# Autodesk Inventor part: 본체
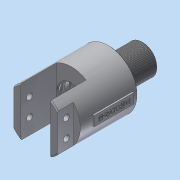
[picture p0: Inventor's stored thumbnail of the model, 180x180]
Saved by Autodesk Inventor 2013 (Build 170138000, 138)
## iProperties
Created: 2019-02
Part Number: 본체
Material: 알루미늄 6061
Document SubType Name: Modeling
Designer: Administrator
Density: 2.71 g/cm^3
Mass: 347.812 g
Surface Area: 290.077 cm^2
Volume: 128.344 cm^3
Author: Administrator
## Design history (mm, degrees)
sketch "스케치1"
  geometry: C1 r 29 at (0, 0); 1 further point
  constraints: 1 centre point, 1 coincident
  dimensions: "d0" = 58 diameter of C1
extrude "돌출1" new body sketch "스케치1" stored distance "d1" = 74; taper "d2" = 0 deg
sketch "스케치6"
  geometry: L1 (22, 18.894)-(22, -18.894); L2 (-22, -18.894)-(-22, 18.894); L3 (0, -29)-(0, 29); A1 r 29 centre (0, 0) between (22, 18.894) and (22, -18.894) reference; A2 r 29 centre (0, 0) between (-22, 18.894) and (-22, -18.894); A3 r 29 centre (0, 0) between (0, 29) and (-22, 18.894); A4 r 29 centre (0, 0) between (-22, -18.894) and (22, -18.894); A5 r 29 centre (0, 0) between (22, -18.894) and (22, 18.894); A6 r 29 centre (0, 0) between (22, 18.894) and (0, 29); 3 further points
  constraints: 16 point on circle, 6 end point, 5 centre point, 4 midpoint, 2 horizontal alignment, 2 parallel, 1 coincident, 1 vertical, 1 other
  dimensions: "d16" = 44 distance between parallel lines of L1 L2
extrude "돌출3" cut sketch "스케치6" distance "d18" = 16; taper "d19" = 0 deg
sketch "스케치7"
  geometry: L1 (22, -18.894)-(22, 18.894) reference; L2 (-22, 18.894)-(-22, -18.894) reference; L3 (-15, -24.819)-(-15, 24.819); L4 (15, 24.819)-(15, -24.819); A1 r 29 centre (0, 0) between (22, 18.894) and (-22, 18.894) reference; A2 r 29 centre (0, 0) between (-22, -18.894) and (22, -18.894) reference; A3 r 29 centre (0, 0) between (-22, 18.894) and (-15, -24.819); A4 r 29 centre (0, 0) between (-15, 24.819) and (-22, 18.894); A5 r 29 centre (0, 0) between (-15, -24.819) and (15, -24.819); A6 r 29 centre (0, 0) between (22, -18.894) and (15, 24.819); A7 r 29 centre (0, 0) between (15, -24.819) and (22, -18.894); A8 r 29 centre (0, 0) between (15, 24.819) and (-15, 24.819)
  constraints: 16 point on circle, 6 centre point, 6 end point, 1 coincident, 1 concentric
  dimensions: "d20" = 7 distance between parallel lines of L3 L2; "d21" = 7 distance between parallel lines of L1 L4 (= d20)
extrude "돌출4" cut sketch "스케치7" distance "d22" = 36; taper "d23" = 0 deg
sketch "스케치9"
  geometry: C1 r 29 at (0, 0) reference; C2 r 13 at (0, 0)
  constraints: 1 centre point, 1 coincident
  dimensions: "d28" = 26 diameter of C2
extrude "돌출5" join sketch "스케치9" distance "d29" = 5; taper "d30" = 0 deg
sketch "스케치10"
  geometry: C1 r 13 at (0, 0) reference; C2 r 15 at (0, 0)
  constraints: 1 centre point, 1 coincident
  dimensions: "d31" = 30 diameter of C2
extrude "돌출6" join sketch "스케치10" distance "d32" = 29; taper "d33" = 0 deg
sketch "스케치11"
  geometry: L1 (37.789, 0)-(0, 0) reference; L2 (37.789, 16)-(0, 16) reference; L3 (18.894, 0)-(18.894, 16); L4 (37.789, 74)-(37.789, 16) reference; L5 (37.789, 16)-(37.789, 0) reference; L6 (37.789, 0)-(0, 0) reference; L7 (0, 0)-(0, 16) reference; L8 (37.789, 16)-(0, 16) reference; L9 (0, 74)-(37.789, 74) reference; L10 (0, 16)-(0, 74) reference; C1 r 3 at (27.894, 9); C2 r 3 at (9.894, 9); 1 further point
  constraints: 2 centre point, 2 end point, 2 midpoint, 1 symmetric about line, 1 other
  dimensions: "d37" = 6 diameter of C1; "d38" = 9 distance from line of C1.centre L1; "d39" = 9 distance from line of C1.centre L3
extrude "돌출7" cut sketch "스케치11" stored distance "d40" = 29; taper "d41" = 0 deg
sketch "스케치12"
  geometry: L1 (-1, -24.819)-(-1, 24.819) reference; L2 (-1, 0)-(-1, 14); L3 (-1, 14)-(1.65, 14); L4 (1.65, 14)-(1.65, 17); L5 (1.65, 17)-(6.35, 17); L6 (6.35, 17)-(6.35, 14); L7 (6.35, 14)-(10.65, 14); L8 (10.65, 14)-(10.65, 17); L9 (10.65, 17)-(15.35, 17); L10 (15.35, 17)-(15.35, 14); L11 (15.35, 14)-(19, 14); L12 (19, 14)-(19, 16); L13 (19, 16)-(26, 16); L14 (71, 7)-(49, 7); L15 (49, 7)-(49, 4); L16 (49, 4)-(26, 4); L17 (26, 4)-(26, 16); L18 (71, -15)-(71, 15) reference; L19 (71, 7)-(71, 0); L20 (-1, 0)-(71, 0); 1 further point
  constraints: 36 end point, 7 parallel, 6 collinear, 3 perpendicular, 2 midpoint, 2 point on line, 1 horizontal alignment
  dimensions: "d48" = 7 distance of L12.end L13.end; "d49" = 4.7 distance of L4.end L5.end; "d50" = 4.7 distance of L8.end L9.end; "d51" = 2.65 distance of L2.end L3.end (computed from d49); "d52" = 4.3 distance of L6.end L7.end; "d54" = 3.65 distance of L10.end L11.end (computed from d49, d50, d52, d51); "d57" = 22 distance of L14.start L14.end; "d58" = 23 distance of L15.end L16.end; "d59" = 12 distance of L16.end L13.end; "d60" = 28 diameter of L3 L20; "d61" = 34 diameter of L5 L20; "d62" = 8 diameter of L16 L20; "d63" = 14 diameter of L14 L20; "d64" = 32 diameter of L13 L20
revolve "회전1" sketch "스케치12" stored, may be unused: angle "d65" = 90 deg
sketch "스케치13"
  geometry: C1 r 7 at (0, 0) reference
hole "구멍1" sketch "스케치13" at (0, 0) diameter "d66" = 11.835; stored, may be unused: countersink angle "d70" = 90 deg, drill point angle "d72" = 118 deg; dims "d67" = 18, "d68" = 4, "d69" = 2, "d71" = 22
sketch "스케치14"
  geometry: C1 r 7 at (0, 0) reference; C2 r 15 at (0, 0) reference; C3 r 7 at (0, 0)
  constraints: 1 centre point, 1 coincident
  dimensions: "d73" = 14 diameter of C3
extrude "돌출8" join sketch "스케치14" distance "d74" = 22; taper "d75" = 0 deg
sketch "스케치15"
  geometry: C1 r 15 at (0, 0) reference
hole "구멍2" sketch "스케치15" at (0, 0) diameter "d76" = 11.835; stored, may be unused: countersink angle "d80" = 90 deg, drill point angle "d82" = 118 deg; dims "d77" = 18, "d78" = 4, "d79" = 2, "d81" = 22
feature "스레드1" dims "d83" = 10, "d84" = 0
chamfer "모따기1" distance "d85" = 1; stored, may be unused: second distance "d86" = 2, angle "d87" = 45 deg
fillet "모깎기1" dims "d88" = 0.8
node "작업 평면1"
node "작업 평면3"
sketch "스케치18"
  geometry: L1 (8, -5)-(-32, -5); L2 (-32, -5)-(-32, 5); L3 (-32, 5)-(8, 5); L4 (8, 5)-(8, -5); L5 (-37, 29)-(-37, -29) reference; 2 further points
  constraints: 8 end point, 2 parallel, 1 horizontal, 1 horizontal alignment, 1 midpoint, 1 perpendicular
  dimensions: "d90" = 40 distance of L2.end L3.end; "d91" = 10 distance of L1.end L2.end; "d92" = 5 distance between parallel lines of L5 L2
extrude "돌출9" join sketch "스케치18" stored distance "d93" = 22; taper "d94" = 0 deg
node "작업 평면4"
sketch "스케치19"
  geometry: L1 (5, -8)-(-5, -8) reference; L2 (-5, -8)-(-5, 32) reference; L3 (-5, 32)-(5, 32) reference; L4 (5, 32)-(5, -8) reference; 2 further points
  constraints: 1 vertical alignment, 1 other
  dimensions: "d96" = 20 distance from line of point (0, 12) L1
feature "엠보싱1" sketch "스케치19" dims "d97" = 0.5, "d98" = 0
chamfer "모따기2" distance "d99" = 1; stored, may be unused: second distance "d100" = 2, angle "d101" = 45 deg
chamfer "모따기3" distance "d102" = 1; stored, may be unused: second distance "d103" = 2, angle "d104" = 45 deg
chamfer "모따기4" distance "d105" = 1; stored, may be unused: second distance "d106" = 2, angle "d107" = 45 deg
chamfer "모따기5" distance "d108" = 1; stored, may be unused: second distance "d109" = 2, angle "d110" = 45 deg
node "솔리드1"
node "절단 모서리 투영4"
other parameters: "d95" = 19.25
